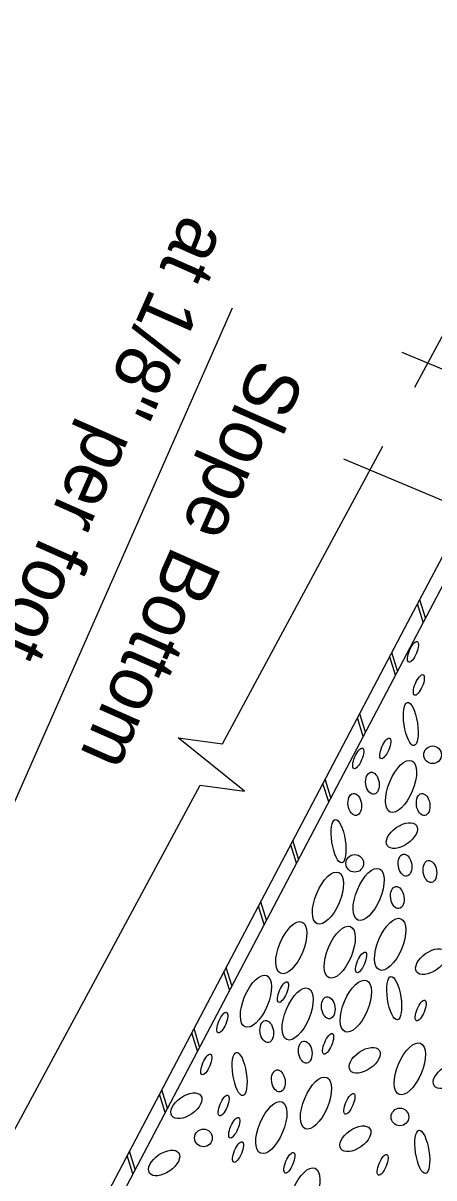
# Model space of a CAD drawing. Extents: x 1968564 to 1968711, y 796599 to 796794.
# Drawn here: x 1968598.8 to 1968602.59, y 796691.24 to 796701.88 of the extents above; entities that cross this region are included whole.
import ezdxf

# ---------------------------------------------------------------- set-up
doc = ezdxf.new("R2010")
doc.units = 0
for name, color, linetype in [('BR_AUTO DIMENSION', 7, 'Continuous'), ('BR_DETAILS', 7, 'Continuous'), ('BR_GROUND LINES', 7, 'Continuous'), ('BR_STRUCTURAL STEEL', 7, 'Continuous'), ('BR_TEXT', 7, 'Continuous')]:
    doc.layers.add(name, color=color, linetype=linetype)

msp = doc.modelspace()

# ---------------------------------------------------------------- linework, layer by layer
at = {"layer": 'BR_AUTO DIMENSION'}
msp.add_line((1968598.238, 796693.598), (1968600.733, 796699.251), dxfattribs=at)
at = {"layer": 'BR_DETAILS'}
for p, q in [((1968602.411, 796698.522), (1968603.412, 796700.381)), ((1968605.546, 796697.476), (1968602.296, 796698.84)), ((1968600.641, 796695.237), (1968602.117, 796697.977)), ((1968605.02, 796696.489), (1968601.757, 796697.858)), ((1968598.407, 796691.09), (1968600.435, 796694.855))]:
    msp.add_line(p, q, dxfattribs=at)
msp.add_lwpolyline([(1968600.435, 796694.855), (1968600.843, 796694.799), (1968600.233, 796695.292), (1968600.641, 796695.237)], dxfattribs=at)
at = {"layer": 'BR_GROUND LINES'}
for centre in [(1968602.575, 796695.135), (1968601.858, 796694.135), (1968602.274, 796691.799), (1968600.465, 796691.606)]:
    msp.add_circle(centre, 0.0812, dxfattribs=at)
for centre, major_axis, ratio in [((1968602.394, 796696.084), (0.0396, 0.0944), 0.335809), ((1968602.448, 796695.778), (0.0396, 0.0944), 0.335809), ((1968602.374, 796695.419), (-0.03, 0.199), 0.307583), ((1968602.139, 796695.194), (0.0396, 0.0944), 0.335809), ((1968601.89, 796695.102), (0.0396, 0.0944), 0.335809), ((1968602.284, 796694.844), (0.099, 0.236), 0.439024), ((1968602.021, 796694.873), (-0.015, 0.101), 0.604846), ((1968601.858, 796694.678), (-0.015, 0.101), 0.604846), ((1968602.488, 796694.677), (-0.015, 0.101), 0.604846), ((1968601.709, 796694.339), (-0.03, 0.199), 0.307583), ((1968602.292, 796694.391), (0.134, 0.093), 0.55), ((1968602.321, 796694.118), (-0.015, 0.101), 0.604846), ((1968602.55, 796694.06), (-0.015, 0.101), 0.604846), ((1968601.611, 796693.815), (0.099, 0.236), 0.439024), ((1968601.986, 796693.849), (0.099, 0.236), 0.439024), ((1968602.25, 796693.82), (-0.015, 0.101), 0.604846), ((1968601.274, 796693.358), (0.099, 0.236), 0.439024), ((1968602.184, 796693.389), (0.099, 0.236), 0.439024), ((1968601.72, 796693.317), (0.099, 0.236), 0.439024), ((1968601.916, 796693.223), (0.0396, 0.0944), 0.335809), ((1968602.562, 796693.23), (0.134, 0.093), 0.55), ((1968600.948, 796692.865), (0.099, 0.236), 0.439024), ((1968601.197, 796692.95), (0.0396, 0.0944), 0.335809), ((1968601.868, 796692.82), (0.099, 0.236), 0.439024), ((1968602.221, 796692.893), (-0.03, 0.199), 0.307583), ((1968601.332, 796692.747), (0.099, 0.236), 0.439024), ((1968601.614, 796692.805), (-0.015, 0.101), 0.604846), ((1968602.465, 796692.779), (0.0396, 0.0944), 0.335809), ((1968600.639, 796692.668), (0.0396, 0.0944), 0.335809), ((1968601.048, 796692.586), (-0.015, 0.101), 0.604846), ((1968601.613, 796692.472), (0.0396, 0.0944), 0.335809), ((1968601.402, 796692.396), (-0.015, 0.101), 0.604846), ((1968601.95, 796692.321), (0.134, 0.093), 0.55), ((1968602.365, 796692.242), (0.099, 0.236), 0.439024), ((1968600.491, 796692.283), (0.0396, 0.0944), 0.335809), ((1968600.798, 796692.195), (-0.03, 0.199), 0.307583), ((1968602.724, 796692.179), (0.134, 0.093), 0.55), ((1968601.155, 796692.131), (-0.015, 0.101), 0.604846), ((1968601.501, 796691.927), (0.099, 0.236), 0.439024), ((1968600.308, 796691.902), (0.134, 0.093), 0.55), ((1968600.651, 796691.904), (0.0396, 0.0944), 0.335809), ((1968601.809, 796691.92), (0.0396, 0.0944), 0.335809), ((1968601.09, 796691.701), (0.099, 0.236), 0.439024), ((1968600.748, 796691.7), (0.0396, 0.0944), 0.335809), ((1968601.864, 796691.598), (0.134, 0.093), 0.55), ((1968602.48, 796691.477), (-0.03, 0.199), 0.307583), ((1968600.783, 796691.476), (0.0396, 0.0944), 0.335809), ((1968600.103, 796691.375), (0.134, 0.093), 0.55), ((1968601.256, 796691.377), (0.0396, 0.0944), 0.335809), ((1968602.115, 796691.358), (0.0396, 0.0944), 0.335809), ((1968601.394, 796691.091), (0.099, 0.236), 0.439024)]:
    msp.add_ellipse(centre, major_axis=major_axis, ratio=ratio, dxfattribs=at)
at = {"layer": 'BR_STRUCTURAL STEEL'}
for p, q in [((1968602.888, 796697.383), (1968602.345, 796696.353)), ((1968603.003, 796697.335), (1968602.456, 796696.295)), ((1968602.509, 796696.396), (1968602.457, 796696.564)), ((1968602.489, 796696.357), (1968602.436, 796696.525)), ((1968602.345, 796696.353), (1968599.164, 796690.308)), ((1968602.456, 796696.295), (1968599.275, 796690.249)), ((1968602.232, 796695.869), (1968602.18, 796696.038)), ((1968602.253, 796695.909), (1968602.201, 796696.077)), ((1968601.956, 796695.344), (1968601.904, 796695.513)), ((1968601.935, 796695.305), (1968601.883, 796695.474)), ((1968601.618, 796694.702), (1968601.565, 796694.871)), ((1968601.638, 796694.741), (1968601.586, 796694.91)), ((1968601.341, 796694.176), (1968601.289, 796694.345)), ((1968601.321, 796694.137), (1968601.269, 796694.306)), ((1968601.024, 796693.573), (1968600.972, 796693.742)), ((1968601.045, 796693.612), (1968600.992, 796693.781)), ((1968600.727, 796693.009), (1968600.675, 796693.177)), ((1968600.706, 796692.97), (1968600.654, 796693.138)), ((1968600.409, 796692.405), (1968600.357, 796692.574)), ((1968600.43, 796692.444), (1968600.378, 796692.613)), ((1968600.112, 796691.841), (1968600.06, 796692.01)), ((1968600.133, 796691.88), (1968600.081, 796692.049)), ((1968599.836, 796691.316), (1968599.784, 796691.484)), ((1968599.815, 796691.276), (1968599.763, 796691.445))]:
    msp.add_line(p, q, dxfattribs=at)

# ---------------------------------------------------------------- texts
at = {"layer": 'BR_TEXT'}
for s, height, rotation, p in [('SECTION H-H', 1.5, 247.246, (1968599.319, 796709.564)), ('at 1/8" per foot', 0.49995, 246.0769, (1968600.284, 796700.13)), ('Slope Bottom', 0.49995, 246.0769, (1968600.95, 796698.808)), ('aggregate drain field.', 0.49995, 247.246, (1968604.882, 796691.556))]:
    msp.add_text(s, height=height, rotation=rotation, dxfattribs=at).set_placement(p)

doc.saveas('drawing.dxf')
